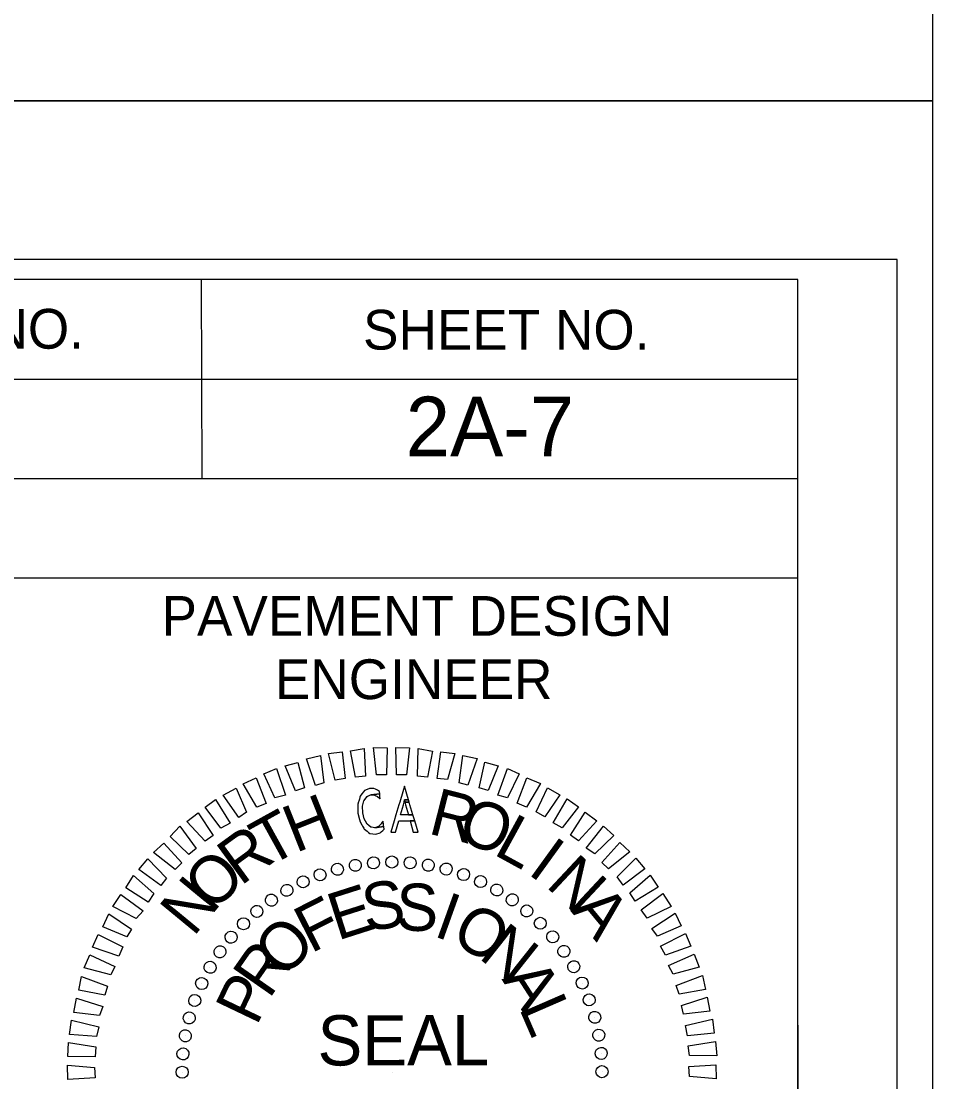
# Model space of a CAD drawing. Extents: x 2320980 to 2456309, y 595047 to 606177.
# Drawn here: x 2456022.57 to 2456045.51, y 596278.89 to 596305.57 of the extents above; entities that cross this region are included whole.
import ezdxf

# ---------------------------------------------------------------- set-up
doc = ezdxf.new("R2010")
doc.units = 0
for name, color, linetype in [('Default', 7, 'Continuous'), ('Sheet Data Field CELL', 7, 'Continuous'), ('Sheet Plan CELL', 7, 'Continuous'), ('Sheet Plot Border Inside CELL', 7, 'Continuous'), ('Sheet Plot Border Outside CELL', 7, 'Continuous')]:
    doc.layers.add(name, color=color, linetype=linetype)

msp = doc.modelspace()

# ---------------------------------------------------------------- linework, layer by layer
at = {"layer": 'Default'}
for p, q in [((2456030.521, 596284.236), (2456030.521, 596284.236)), ((2456030.521, 596284.236), (2456030.521, 596284.236)), ((2456030.972, 596284.328), (2456030.972, 596284.328)), ((2456030.972, 596284.328), (2456030.972, 596284.328)), ((2456031.424, 596284.4), (2456031.424, 596284.4)), ((2456031.424, 596284.4), (2456031.424, 596284.4)), ((2456031.887, 596284.419), (2456031.887, 596284.419)), ((2456031.887, 596284.419), (2456031.887, 596284.419)), ((2456032.351, 596284.396), (2456032.351, 596284.396)), ((2456032.351, 596284.396), (2456032.351, 596284.396)), ((2456032.805, 596284.331), (2456032.805, 596284.331)), ((2456032.805, 596284.331), (2456032.805, 596284.331)), ((2456033.259, 596284.245), (2456033.259, 596284.245)), ((2456033.259, 596284.245), (2456033.259, 596284.245)), ((2456030.081, 596284.101), (2456030.081, 596284.101)), ((2456030.081, 596284.101), (2456030.081, 596284.101)), ((2456033.704, 596284.106), (2456033.704, 596284.106)), ((2456033.704, 596284.106), (2456033.704, 596284.106)), ((2456029.256, 596283.706), (2456029.256, 596283.706)), ((2456029.256, 596283.706), (2456029.256, 596283.706)), ((2456029.652, 596283.924), (2456029.652, 596283.924)), ((2456029.652, 596283.924), (2456029.652, 596283.924)), ((2456034.118, 596283.924), (2456034.118, 596283.924)), ((2456034.118, 596283.924), (2456034.118, 596283.924)), ((2456034.544, 596283.722), (2456034.544, 596283.722)), ((2456034.544, 596283.722), (2456034.544, 596283.722)), ((2456028.85, 596283.456), (2456028.85, 596283.456)), ((2456028.85, 596283.456), (2456028.85, 596283.456)), ((2456034.917, 596283.465), (2456034.917, 596283.465)), ((2456034.917, 596283.465), (2456034.917, 596283.465)), ((2456028.497, 596283.186), (2456028.497, 596283.186)), ((2456028.497, 596283.186), (2456028.497, 596283.186)), ((2456035.302, 596283.188), (2456035.302, 596283.188)), ((2456035.302, 596283.188), (2456035.302, 596283.188)), ((2456035.634, 596282.878), (2456035.634, 596282.878)), ((2456035.634, 596282.878), (2456035.634, 596282.878)), ((2456028.155, 596282.863), (2456028.155, 596282.863)), ((2456028.155, 596282.863), (2456028.155, 596282.863)), ((2456027.845, 596282.532), (2456027.845, 596282.532)), ((2456027.845, 596282.532), (2456027.845, 596282.532)), ((2456035.957, 596282.526), (2456035.957, 596282.526)), ((2456035.957, 596282.526), (2456035.957, 596282.526)), ((2456027.557, 596282.157), (2456027.557, 596282.157)), ((2456027.557, 596282.157), (2456027.557, 596282.157)), ((2456036.227, 596282.173), (2456036.227, 596282.173)), ((2456036.227, 596282.173), (2456036.227, 596282.173)), ((2456027.302, 596281.773), (2456027.302, 596281.773)), ((2456027.302, 596281.773), (2456027.302, 596281.773)), ((2456036.476, 596281.777), (2456036.476, 596281.777)), ((2456036.476, 596281.777), (2456036.476, 596281.777)), ((2456027.099, 596281.358), (2456027.099, 596281.358)), ((2456027.099, 596281.358), (2456027.099, 596281.358)), ((2456036.684, 596281.371), (2456036.684, 596281.371)), ((2456036.684, 596281.371), (2456036.684, 596281.371)), ((2456026.917, 596280.933), (2456026.917, 596280.933)), ((2456026.917, 596280.933), (2456026.917, 596280.933)), ((2456036.86, 596280.953), (2456036.86, 596280.953)), ((2456036.86, 596280.953), (2456036.86, 596280.953)), ((2456026.779, 596280.489), (2456026.779, 596280.489)), ((2456026.779, 596280.489), (2456026.779, 596280.489)), ((2456037.006, 596280.513), (2456037.006, 596280.513)), ((2456037.006, 596280.513), (2456037.006, 596280.513)), ((2456026.692, 596280.044), (2456026.692, 596280.044)), ((2456026.692, 596280.044), (2456026.692, 596280.044)), ((2456037.099, 596280.051), (2456037.099, 596280.051)), ((2456037.099, 596280.051), (2456037.099, 596280.051)), ((2456026.638, 596279.58), (2456026.638, 596279.58)), ((2456026.638, 596279.58), (2456026.638, 596279.58)), ((2456037.17, 596279.6), (2456037.17, 596279.6)), ((2456037.17, 596279.6), (2456037.17, 596279.6)), ((2456037.189, 596279.136), (2456037.189, 596279.136)), ((2456037.189, 596279.136), (2456037.189, 596279.136)), ((2456026.615, 596279.116), (2456026.615, 596279.116)), ((2456026.615, 596279.116), (2456026.615, 596279.116)), ((2456031.902, 596279.132), (2456031.902, 596279.132)), ((2456031.902, 596279.132), (2456031.902, 596279.132))]:
    msp.add_line(p, q, dxfattribs=at)
for points in [[(2456030.468, 596286.478), (2456030.297, 596287.149), (2456030.644, 596287.187), (2456030.72, 596286.514)], [(2456030.983, 596286.55), (2456030.854, 596287.212), (2456031.201, 596287.271), (2456031.235, 596286.577)], [(2456031.508, 596286.613), (2456031.432, 596287.297), (2456031.779, 596287.293), (2456031.761, 596286.607)], [(2456032.014, 596286.613), (2456031.99, 596287.297), (2456032.338, 596287.293), (2456032.266, 596286.607)], [(2456032.541, 596286.58), (2456032.56, 596287.276), (2456032.919, 596287.209), (2456032.794, 596286.554)], [(2456033.037, 596286.516), (2456033.13, 596287.192), (2456033.478, 596287.146), (2456033.291, 596286.489)], [(2456029.472, 596286.206), (2456029.208, 596286.833), (2456029.532, 596286.924), (2456029.692, 596286.284)], [(2456029.975, 596286.342), (2456029.742, 596287.012), (2456030.098, 596287.093), (2456030.185, 596286.41)], [(2456033.587, 596286.41), (2456033.68, 596287.097), (2456034.039, 596287.019), (2456033.809, 596286.352)], [(2456034.095, 596286.283), (2456034.23, 596286.928), (2456034.569, 596286.84), (2456034.318, 596286.214)], [(2456028.949, 596286.028), (2456028.674, 596286.634), (2456028.988, 596286.766), (2456029.221, 596286.097)], [(2456034.562, 596286.102), (2456034.802, 596286.77), (2456035.099, 596286.639), (2456034.806, 596286.033)], [(2456028.5, 596285.798), (2456028.152, 596286.381), (2456028.476, 596286.535), (2456028.731, 596285.887)], [(2456035.05, 596285.901), (2456035.291, 596286.537), (2456035.631, 596286.396), (2456035.284, 596285.8)], [(2456028.042, 596285.537), (2456027.652, 596286.098), (2456027.975, 596286.273), (2456028.239, 596285.667)], [(2456031.415, 596285.125), (2456031.492, 596285.114), (2456031.597, 596285.148), (2456031.626, 596285.172), (2456031.667, 596285.206), (2456031.698, 596285.245), (2456031.69, 596285.305), (2456031.69, 596285.307), (2456031.463, 596285.278), (2456031.382, 596285.291), (2456031.368, 596285.294), (2456031.312, 596285.338), (2456031.273, 596285.368), (2456031.232, 596285.441), (2456031.199, 596285.502), (2456031.161, 596285.658), (2456031.161, 596285.658), (2456031.159, 596285.823), (2456031.176, 596285.89), (2456031.192, 596285.952), (2456031.195, 596285.966), (2456031.237, 596286.022), (2456031.27, 596286.065), (2456031.3, 596286.078), (2456031.365, 596286.106), (2456031.589, 596286.135), (2456031.589, 596286.135), (2456031.584, 596286.187), (2456031.53, 596286.226), (2456031.481, 596286.248), (2456031.444, 596286.264), (2456031.329, 596286.269), (2456031.271, 596286.242), (2456031.204, 596286.212), (2456031.18, 596286.181), (2456031.141, 596286.13), (2456031.097, 596286.072), (2456031.096, 596286.072), (2456031.091, 596286.051), (2456031.088, 596286.042), (2456031.077, 596286.002), (2456031.062, 596285.948), (2456031.058, 596285.935), (2456031.041, 596285.873), (2456031.041, 596285.808), (2456031.042, 596285.643), (2456031.042, 596285.642), (2456031.081, 596285.487), (2456031.098, 596285.424), (2456031.14, 596285.351), (2456031.159, 596285.318), (2456031.186, 596285.27), (2456031.188, 596285.267), (2456031.201, 596285.245), (2456031.202, 596285.243), (2456031.27, 596285.19), (2456031.309, 596285.16), (2456031.341, 596285.135)], [(2456031.589, 596286.016), (2456031.602, 596286.005), (2456031.6, 596286.017), (2456031.595, 596286.068), (2456031.592, 596286.106), (2456031.592, 596286.106), (2456031.591, 596286.115), (2456031.589, 596286.135), (2456031.365, 596286.106), (2456031.46, 596286.099), (2456031.475, 596286.091), (2456031.537, 596286.061)], [(2456031.952, 596285.453), (2456031.868, 596285.167), (2456031.989, 596285.167), (2456032.071, 596285.454), (2456032.469, 596285.454), (2456032.424, 596285.605), (2456032.113, 596285.604), (2456032.185, 596285.857), (2456032.186, 596285.858), (2456032.2, 596285.922), (2456032.201, 596285.923), (2456032.211, 596285.984), (2456032.31, 596285.984), (2456032.209, 596286.322), (2456032.109, 596285.984), (2456032.091, 596285.923), (2456032.091, 596285.921), (2456032.072, 596285.858), (2456032.072, 596285.857), (2456031.997, 596285.604)], [(2456035.529, 596285.678), (2456035.812, 596286.284), (2456036.12, 596286.11), (2456035.741, 596285.556)], [(2456027.594, 596285.265), (2456027.194, 596285.795), (2456027.454, 596285.989), (2456027.824, 596285.396)], [(2456032.211, 596285.984), (2456032.223, 596285.923), (2456032.329, 596285.924), (2456032.31, 596285.984)], [(2456032.238, 596285.858), (2456032.31, 596285.605), (2456032.424, 596285.605), (2456032.348, 596285.858), (2456032.348, 596285.858), (2456032.329, 596285.922), (2456032.329, 596285.924), (2456032.223, 596285.923), (2456032.223, 596285.922), (2456032.238, 596285.858)], [(2456035.955, 596285.402), (2456036.302, 596286.009), (2456036.59, 596285.803), (2456036.179, 596285.28)], [(2456027.2, 596284.942), (2456026.737, 596285.439), (2456027.018, 596285.654), (2456027.397, 596285.082)], [(2456036.393, 596285.094), (2456036.761, 596285.67), (2456037.05, 596285.454), (2456036.595, 596284.95)], [(2456026.785, 596284.607), (2456026.313, 596285.062), (2456026.56, 596285.319), (2456026.972, 596284.758)], [(2456031.558, 596285.314), (2456031.463, 596285.278), (2456031.69, 596285.307), (2456031.687, 596285.331), (2456031.686, 596285.334), (2456031.68, 596285.385), (2456031.675, 596285.42), (2456031.672, 596285.446), (2456031.672, 596285.446), (2456031.653, 596285.417), (2456031.627, 596285.378), (2456031.563, 596285.319)], [(2456032.352, 596285.454), (2456032.433, 596285.168), (2456032.555, 596285.168), (2456032.469, 596285.454)], [(2456036.788, 596284.764), (2456037.221, 596285.32), (2456037.478, 596285.083), (2456037.002, 596284.621)], [(2456026.444, 596284.232), (2456025.899, 596284.654), (2456026.158, 596284.89), (2456026.61, 596284.393)], [(2456037.175, 596284.403), (2456037.629, 596284.907), (2456037.886, 596284.67), (2456037.346, 596284.248)], [(2456026.084, 596283.825), (2456025.528, 596284.225), (2456025.755, 596284.493), (2456026.227, 596284.007)], [(2456037.561, 596284.042), (2456038.036, 596284.514), (2456038.262, 596284.244), (2456037.712, 596283.833)], [(2456025.765, 596283.408), (2456025.199, 596283.766), (2456025.394, 596284.075), (2456025.908, 596283.622)], [(2456037.884, 596283.637), (2456038.392, 596284.089), (2456038.598, 596283.787), (2456038.015, 596283.429)], [(2456025.457, 596282.992), (2456024.871, 596283.296), (2456025.076, 596283.595), (2456025.632, 596283.184)], [(2456038.166, 596283.21), (2456038.717, 596283.621), (2456038.923, 596283.298), (2456038.318, 596283.003)], [(2456025.223, 596282.534), (2456024.617, 596282.786), (2456024.769, 596283.116), (2456025.346, 596282.726)], [(2456038.438, 596282.742), (2456039.021, 596283.132), (2456039.175, 596282.808), (2456038.579, 596282.554)], [(2456038.657, 596282.303), (2456039.283, 596282.621), (2456039.416, 596282.296), (2456038.778, 596282.074)], [(2456025.021, 596282.045), (2456024.364, 596282.276), (2456024.505, 596282.594), (2456025.122, 596282.279)], [(2456024.82, 596281.579), (2456024.152, 596281.755), (2456024.294, 596282.085), (2456024.921, 596281.791)], [(2456038.856, 596281.812), (2456039.504, 596282.098), (2456039.626, 596281.773), (2456038.976, 596281.593)], [(2456039.045, 596281.31), (2456039.714, 596281.565), (2456039.784, 596281.208), (2456039.123, 596281.09)], [(2456024.671, 596281.07), (2456024.015, 596281.194), (2456024.083, 596281.533), (2456024.741, 596281.293)], [(2456039.18, 596280.807), (2456039.829, 596281.019), (2456039.899, 596280.663), (2456039.237, 596280.587)], [(2456024.533, 596280.551), (2456023.889, 596280.634), (2456023.956, 596280.994), (2456024.624, 596280.785)], [(2456024.459, 596280.023), (2456023.784, 596280.074), (2456023.83, 596280.433), (2456024.518, 596280.267)], [(2456039.285, 596280.303), (2456039.966, 596280.463), (2456040.005, 596280.106), (2456039.332, 596280.041)], [(2456024.426, 596279.517), (2456023.742, 596279.525), (2456023.756, 596279.873), (2456024.443, 596279.77)], [(2456039.347, 596279.788), (2456040.041, 596279.896), (2456040.069, 596279.538), (2456039.384, 596279.547)], [(2456024.426, 596278.99), (2456023.742, 596278.946), (2456023.735, 596279.305), (2456024.411, 596279.243)], [(2456039.367, 596279.272), (2456040.051, 596279.317), (2456040.058, 596278.959), (2456039.383, 596279.02)]]:
    msp.add_lwpolyline(points, close=True, dxfattribs=at)
for centre, major_axis in [((2456030.975, 596284.334), (-0.027, 0.149)), ((2456031.432, 596284.395), (-0.013, 0.151)), ((2456031.892, 596284.416), (0, 0.152)), ((2456032.353, 596284.396), (0.013, 0.151)), ((2456032.81, 596284.337), (0.026, 0.149)), ((2456030.086, 596284.095), (-0.052, 0.142)), ((2456030.525, 596284.234), (-0.039, 0.146)), ((2456033.26, 596284.238), (0.039, 0.147)), ((2456033.7, 596284.1), (0.052, 0.143)), ((2456029.66, 596283.918), (-0.064, 0.137)), ((2456034.126, 596283.924), (0.064, 0.138)), ((2456029.252, 596283.704), (-0.076, 0.131)), ((2456034.535, 596283.712), (0.076, 0.131)), ((2456028.864, 596283.456), (-0.087, 0.124)), ((2456034.924, 596283.465), (0.087, 0.124)), ((2456028.498, 596283.175), (-0.098, 0.116)), ((2456035.29, 596283.185), (0.097, 0.116)), ((2456028.159, 596282.863), (-0.107, 0.107)), ((2456035.63, 596282.874), (0.107, 0.107)), ((2456027.848, 596282.523), (-0.116, 0.097)), ((2456035.942, 596282.534), (0.116, 0.098)), ((2456036.223, 596282.169), (0.124, 0.087)), ((2456027.568, 596282.157), (-0.124, 0.087)), ((2456027.321, 596281.768), (-0.131, 0.076)), ((2456036.471, 596281.781), (0.131, 0.076)), ((2456036.684, 596281.372), (0.137, 0.064)), ((2456027.109, 596281.359), (-0.138, 0.064)), ((2456026.933, 596280.933), (-0.143, 0.052)), ((2456036.861, 596280.947), (0.142, 0.052)), ((2456026.795, 596280.493), (-0.147, 0.039)), ((2456037, 596280.508), (0.146, 0.039)), ((2456026.696, 596280.043), (-0.149, 0.026)), ((2456037.101, 596280.058), (0.149, 0.027)), ((2456026.637, 596279.586), (-0.151, 0.013)), ((2456037.162, 596279.601), (0.151, 0.013)), ((2456026.617, 596279.126), (-0.152, 0)), ((2456037.182, 596279.141), (0.152, 0))]:
    msp.add_ellipse(centre, major_axis=major_axis, ratio=0.999708, dxfattribs=at)
at = {"layer": 'Sheet Plan CELL'}
for p, q in [((2456027.099, 596299.064), (2456027.109, 596294.064)), ((2456002.094, 596296.569), (2456042.104, 596296.566)), ((2456002.097, 596294.061), (2456042.104, 596294.066))]:
    msp.add_line(p, q, dxfattribs=at)
for points in [[(2456042.112, 596299.076), (2455742.104, 596299.076), (2455742.104, 596089.076), (2456042.107, 596089.076)], [(2456022.107, 596291.564), (2456042.104, 596291.566), (2456042.107, 596269.064), (2456022.107, 596269.061)]]:
    msp.add_lwpolyline(points, close=True, dxfattribs=at)
at = {"layer": 'Sheet Plot Border Inside CELL'}
msp.add_lwpolyline([(2455711.407, 596088.574), (2456044.604, 596088.576), (2456044.607, 596299.574), (2455711.407, 596299.574)], close=True, dxfattribs=at)
at = {"layer": 'Sheet Plot Border Outside CELL'}
for points in [[(2455708.807, 596303.574), (2456045.507, 596303.574), (2456045.507, 596522.574), (2455708.807, 596522.574)], [(2455708.807, 596084.574), (2456045.507, 596084.574), (2456045.507, 596303.574), (2455708.807, 596303.574)]]:
    msp.add_lwpolyline(points, close=True, dxfattribs=at)

# ---------------------------------------------------------------- texts
at = {"layer": 'Default'}
for s, height, rotation, p in [('H', 1.188, 21.7004, (2456029.47, 596284.637)), ('R', 1.188, 345.702, (2456032.778, 596285.142)), ('O', 1.188, 338.5021, (2456033.487, 596284.997)), ('T', 1.188, 28.9007, (2456028.782, 596284.276)), ('L', 1.188, 331.3018, (2456034.421, 596284.625)), ('R', 1.188, 36.1015, (2456028.085, 596283.799)), ('I', 1.187, 324.1011, (2456035.284, 596284.136)), ('O', 1.188, 43.3027, (2456027.37, 596283.133)), ('N', 1.188, 316.8999, (2456035.742, 596283.817)), ('N', 1.188, 50.5045, (2456026.898, 596282.513)), ('S', 1.188, 8.3366, (2456031.235, 596282.668)), ('E', 1.188, 17.692, (2456030.523, 596282.434)), ('S', 1.188, 358.9814, (2456031.993, 596282.694)), ('F', 1.187, 27.048, (2456029.855, 596282.105)), ('I', 1.188, 340.2706, (2456032.911, 596282.563)), ('A', 1.188, 309.6981, (2456036.376, 596283.197)), ('A', 1.188, 309.6981, (2456036.376, 596283.197)), ('O', 1.188, 330.9144, (2456033.335, 596282.424)), ('O', 1.188, 45.7622, (2456029.172, 596281.46)), ('N', 1.188, 321.5576, (2456034.049, 596282.016)), ('R', 1.188, 55.1206, (2456028.803, 596280.948)), ('P', 1.188, 64.4798, (2456028.489, 596280.268)), ('A', 1.188, 302.8412, (2456034.649, 596281.469)), ('L', 1.188, 293.4818, (2456035.084, 596280.751)), ('SEAL', 1.2634, 0.081, (2456030.024, 596279.296))]:
    msp.add_text(s, height=height, rotation=rotation, dxfattribs=at).set_placement(p)
at = {"layer": 'Sheet Data Field CELL'}
msp.add_text('2A-7', height=1.5, rotation=0, dxfattribs=at).set_placement((2456032.244, 596294.626))
at = {"layer": 'Sheet Plan CELL'}
for s, height, p in [('PROJECT REFERENCE NO.', 1.00002, (2456006.537, 596297.334)), ('SHEET NO.', 1, (2456031.169, 596297.311)), ('PAVEMENT DESIGN', 1.00002, (2456026.098, 596290.109)), ('ENGINEER', 1, (2456028.952, 596288.516))]:
    msp.add_text(s, height=height, rotation=0, dxfattribs=at).set_placement(p)

doc.saveas('drawing.dxf')
